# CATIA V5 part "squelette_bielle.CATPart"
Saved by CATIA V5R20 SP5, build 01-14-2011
Part number: squelette_bielle
Publications: "Longueur_bielle", "diametre_int", "diametre_ext", "largeur", "epaisseur", "Plan.1", "Point.1", "Point.2", "Point.3", "Plan.2", "Point.4", "Point.5", "Droite.1", "Plan.3", "Plan.4", "Droite.2", "Droite.3"
Bounding box of the stored display mesh (mm): x -5 to 5, y -37.5 to 37.5, z -5 to 5
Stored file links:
  F:\iao\catia\projet iao\squelette_bielle.CATPart
  F:\iao\catia\projet iao\fhartmann.CATProduct
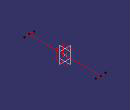
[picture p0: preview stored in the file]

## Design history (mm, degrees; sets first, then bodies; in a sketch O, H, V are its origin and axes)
Parameters
  Longueur_bielle = 75 mm {= External.bielle_longueur}
  diametre_int = 10 mm {= External.bielle_diametre_int}
  diametre_ext = 20 mm {= External.bielle_diametre_ext}
  largeur = 10 mm
  epaisseur = 6.61 mm {= External.bielle1_epaisseur}
External parameters (linked from other documents)
  External.bielle_longueur = 75 mm
  External.bielle_diametre_int = 10 mm
  External.bielle_diametre_ext = 20 mm
  External.bielle1_epaisseur = 6.61 mm
Set1
  Plane1: type Offset, RefPlane yz-plane, Offset 0
  Point1: type OnPlane, Support Plane1, H 0, V 0, Direction (0, 1, 0)
  Point2: type OnPlane, Support Plane1, H 37.5 {= Longueur_bielle/2}, V 0, Direction (0, 1, 0)
  Point3: type OnPlane, Support Plane1, H -37.5 {= -Longueur_bielle/2}, V 0, Direction (0, 1, 0)
  Plane2: type Offset, RefPlane zx-plane, Offset 0
  Point4: type OnPlane, Support Plane2, H 3.305 {= epaisseur/2}, V 5 {= largeur/2}, Direction (-1, 0, 0)
  Point5: type OnPlane, Support Plane2, H -3.305 {= -epaisseur/2}, V -5 {= -largeur/2}, Direction (-1, 0, 0)
  Line1: type PtPt, FirstPoint Point3, SecondPoint Point2
  Plane3: type Offset, RefPlane Plane1, Offset 3.305 {= epaisseur/2}
  Plane4: type Offset, RefPlane Plane1, Offset 3.305 {= epaisseur/2}, reversed
  Line2: type Normal, RefPoint Point2, RefSkin Plane1, Start -5, End 5
  Line3: type Normal, RefPoint Point3, RefSkin Plane1, Start -5, End 5
Body1 (main body)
